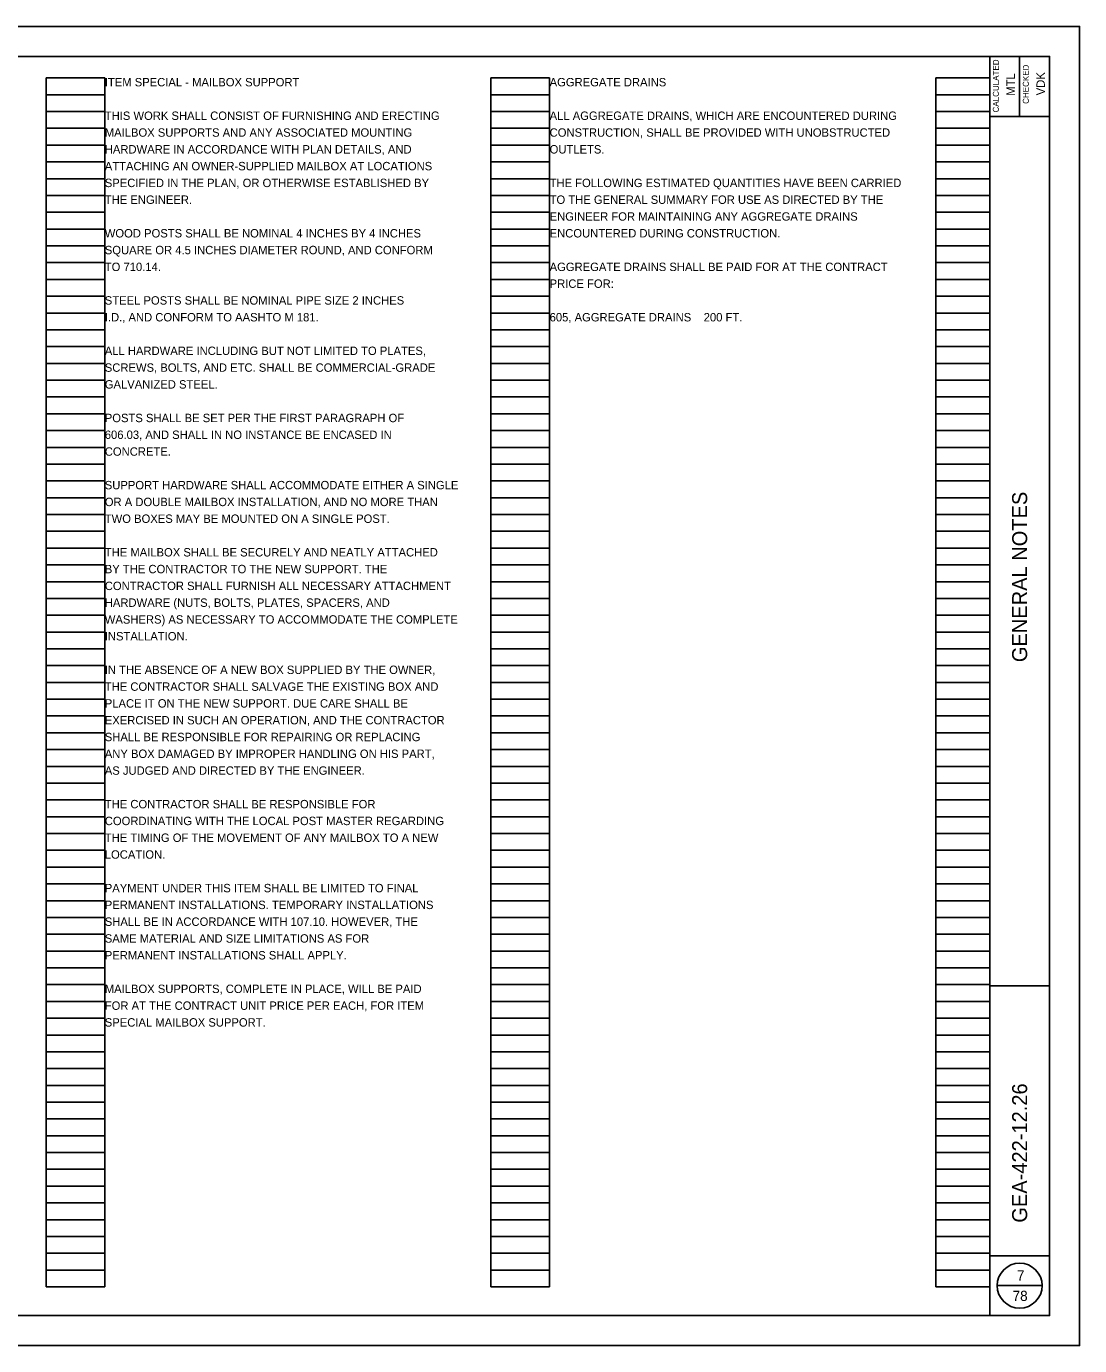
# Model space of a CAD drawing. Extents: x -13.7 to 20.3, y -10.6 to 11.4.
# Drawn here: x 2.73 to 20.3, y -10.63 to 11.37 of the extents above; entities that cross this region are included whole.
import ezdxf

# ---------------------------------------------------------------- set-up
doc = ezdxf.new("R2010")
doc.units = 0
for name, color, linetype in [('SC_Scratch1', 7, 'Continuous'), ('SH_Border', 7, 'Continuous'), ('SH_Cut_Line', 7, 'Continuous'), ('SH_Data', 7, 'Continuous'), ('SH_Text', 7, 'Continuous')]:
    doc.layers.add(name, color=color, linetype=linetype)

msp = doc.modelspace()

# ---------------------------------------------------------------- linework, layer by layer
at = {"layer": 'SC_Scratch1'}
for p, q in [((3.061, -9.649), (3.061, 10.511)), ((3.061, 10.511), (4.041, 10.511)), ((4.041, -9.649), (4.041, 10.511)), ((10.481, -9.649), (10.481, 10.511)), ((10.481, 10.511), (11.461, 10.511)), ((11.461, -9.649), (11.461, 10.511)), ((17.901, -9.649), (17.901, 10.511)), ((17.901, 10.511), (18.801, 10.511)), ((18.801, -9.649), (18.801, 10.511)), ((3.061, 10.231), (4.041, 10.231)), ((10.481, 10.231), (11.461, 10.231)), ((17.901, 10.231), (18.801, 10.231)), ((3.061, 9.951), (4.041, 9.951)), ((10.481, 9.951), (11.461, 9.951)), ((17.901, 9.951), (18.801, 9.951)), ((3.061, 9.671), (4.041, 9.671)), ((10.481, 9.671), (11.461, 9.671)), ((17.901, 9.671), (18.801, 9.671)), ((3.061, 9.391), (4.041, 9.391)), ((10.481, 9.391), (11.461, 9.391)), ((17.901, 9.391), (18.801, 9.391)), ((3.061, 9.111), (4.041, 9.111)), ((10.481, 9.111), (11.461, 9.111)), ((17.901, 9.111), (18.801, 9.111)), ((3.061, 8.831), (4.041, 8.831)), ((10.481, 8.831), (11.461, 8.831)), ((17.901, 8.831), (18.801, 8.831)), ((3.061, 8.551), (4.041, 8.551)), ((10.481, 8.551), (11.461, 8.551)), ((17.901, 8.551), (18.801, 8.551)), ((3.061, 8.271), (4.041, 8.271)), ((10.481, 8.271), (11.461, 8.271)), ((17.901, 8.271), (18.801, 8.271)), ((3.061, 7.991), (4.041, 7.991)), ((10.481, 7.991), (11.461, 7.991)), ((17.901, 7.991), (18.801, 7.991)), ((3.061, 7.711), (4.041, 7.711)), ((10.481, 7.711), (11.461, 7.711)), ((17.901, 7.711), (18.801, 7.711)), ((3.061, 7.431), (4.041, 7.431)), ((10.481, 7.431), (11.461, 7.431)), ((17.901, 7.431), (18.801, 7.431)), ((3.061, 7.151), (4.041, 7.151)), ((10.481, 7.151), (11.461, 7.151)), ((17.901, 7.151), (18.801, 7.151)), ((3.061, 6.871), (4.041, 6.871)), ((10.481, 6.871), (11.461, 6.871)), ((17.901, 6.871), (18.801, 6.871)), ((3.061, 6.591), (4.041, 6.591)), ((10.481, 6.591), (11.461, 6.591)), ((17.901, 6.591), (18.801, 6.591)), ((3.061, 6.311), (4.041, 6.311)), ((10.481, 6.311), (11.461, 6.311)), ((17.901, 6.311), (18.801, 6.311)), ((3.061, 6.031), (4.041, 6.031)), ((10.481, 6.031), (11.461, 6.031)), ((17.901, 6.031), (18.801, 6.031)), ((3.061, 5.751), (4.041, 5.751)), ((10.481, 5.751), (11.461, 5.751)), ((17.901, 5.751), (18.801, 5.751)), ((3.061, 5.471), (4.041, 5.471)), ((10.481, 5.471), (11.461, 5.471)), ((17.901, 5.471), (18.801, 5.471)), ((3.061, 5.191), (4.041, 5.191)), ((10.481, 5.191), (11.461, 5.191)), ((17.901, 5.191), (18.801, 5.191)), ((3.061, 4.911), (4.041, 4.911)), ((10.481, 4.911), (11.461, 4.911)), ((17.901, 4.911), (18.801, 4.911)), ((3.061, 4.631), (4.041, 4.631)), ((10.481, 4.631), (11.461, 4.631)), ((17.901, 4.631), (18.801, 4.631)), ((3.061, 4.351), (4.041, 4.351)), ((10.481, 4.351), (11.461, 4.351)), ((17.901, 4.351), (18.801, 4.351)), ((3.061, 4.071), (4.041, 4.071)), ((10.481, 4.071), (11.461, 4.071)), ((17.901, 4.071), (18.801, 4.071)), ((3.061, 3.791), (4.041, 3.791)), ((10.481, 3.791), (11.461, 3.791)), ((17.901, 3.791), (18.801, 3.791)), ((3.061, 3.511), (4.041, 3.511)), ((10.481, 3.511), (11.461, 3.511)), ((17.901, 3.511), (18.801, 3.511)), ((3.061, 3.231), (4.041, 3.231)), ((10.481, 3.231), (11.461, 3.231)), ((17.901, 3.231), (18.801, 3.231)), ((3.061, 2.951), (4.041, 2.951)), ((10.481, 2.951), (11.461, 2.951)), ((17.901, 2.951), (18.801, 2.951)), ((3.061, 2.671), (4.041, 2.671)), ((10.481, 2.671), (11.461, 2.671)), ((17.901, 2.671), (18.801, 2.671)), ((3.061, 2.391), (4.041, 2.391)), ((10.481, 2.391), (11.461, 2.391)), ((17.901, 2.391), (18.801, 2.391)), ((3.061, 2.111), (4.041, 2.111)), ((10.481, 2.111), (11.461, 2.111)), ((17.901, 2.111), (18.801, 2.111)), ((3.061, 1.831), (4.041, 1.831)), ((10.481, 1.831), (11.461, 1.831)), ((17.901, 1.831), (18.801, 1.831)), ((3.061, 1.551), (4.041, 1.551)), ((10.481, 1.551), (11.461, 1.551)), ((17.901, 1.551), (18.801, 1.551)), ((3.061, 1.271), (4.041, 1.271)), ((10.481, 1.271), (11.461, 1.271)), ((17.901, 1.271), (18.801, 1.271)), ((3.061, 0.991), (4.041, 0.991)), ((10.481, 0.991), (11.461, 0.991)), ((17.901, 0.991), (18.801, 0.991)), ((3.061, 0.711), (4.041, 0.711)), ((10.481, 0.711), (11.461, 0.711)), ((17.901, 0.711), (18.801, 0.711)), ((3.061, 0.431), (4.041, 0.431)), ((10.481, 0.431), (11.461, 0.431)), ((17.901, 0.431), (18.801, 0.431)), ((3.061, 0.151), (4.041, 0.151)), ((10.481, 0.151), (11.461, 0.151)), ((17.901, 0.151), (18.801, 0.151)), ((3.061, -0.129), (4.041, -0.129)), ((10.481, -0.129), (11.461, -0.129)), ((17.901, -0.129), (18.801, -0.129)), ((3.061, -0.409), (4.041, -0.409)), ((10.481, -0.409), (11.461, -0.409)), ((17.901, -0.409), (18.801, -0.409)), ((3.061, -0.689), (4.041, -0.689)), ((10.481, -0.689), (11.461, -0.689)), ((17.901, -0.689), (18.801, -0.689)), ((3.061, -0.969), (4.041, -0.969)), ((10.481, -0.969), (11.461, -0.969)), ((17.901, -0.969), (18.801, -0.969)), ((3.061, -1.249), (4.041, -1.249)), ((10.481, -1.249), (11.461, -1.249)), ((17.901, -1.249), (18.801, -1.249)), ((3.061, -1.529), (4.041, -1.529)), ((10.481, -1.529), (11.461, -1.529)), ((17.901, -1.529), (18.801, -1.529)), ((3.061, -1.809), (4.041, -1.809)), ((10.481, -1.809), (11.461, -1.809)), ((17.901, -1.809), (18.801, -1.809)), ((3.061, -2.089), (4.041, -2.089)), ((10.481, -2.089), (11.461, -2.089)), ((17.901, -2.089), (18.801, -2.089)), ((3.061, -2.369), (4.041, -2.369)), ((10.481, -2.369), (11.461, -2.369)), ((17.901, -2.369), (18.801, -2.369)), ((3.061, -2.649), (4.041, -2.649)), ((10.481, -2.649), (11.461, -2.649)), ((17.901, -2.649), (18.801, -2.649)), ((3.061, -2.929), (4.041, -2.929)), ((10.481, -2.929), (11.461, -2.929)), ((17.901, -2.929), (18.801, -2.929)), ((3.061, -3.209), (4.041, -3.209)), ((10.481, -3.209), (11.461, -3.209)), ((17.901, -3.209), (18.801, -3.209)), ((3.061, -3.489), (4.041, -3.489)), ((10.481, -3.489), (11.461, -3.489)), ((17.901, -3.489), (18.801, -3.489)), ((3.061, -3.769), (4.041, -3.769)), ((10.481, -3.769), (11.461, -3.769)), ((17.901, -3.769), (18.801, -3.769)), ((3.061, -4.049), (4.041, -4.049)), ((10.481, -4.049), (11.461, -4.049)), ((17.901, -4.049), (18.801, -4.049)), ((3.061, -4.329), (4.041, -4.329)), ((10.481, -4.329), (11.461, -4.329)), ((17.901, -4.329), (18.801, -4.329)), ((3.061, -4.609), (4.041, -4.609)), ((10.481, -4.609), (11.461, -4.609)), ((17.901, -4.609), (18.801, -4.609)), ((3.061, -4.889), (4.041, -4.889)), ((10.481, -4.889), (11.461, -4.889)), ((17.901, -4.889), (18.801, -4.889)), ((3.061, -5.169), (4.041, -5.169)), ((10.481, -5.169), (11.461, -5.169)), ((17.901, -5.169), (18.801, -5.169)), ((3.061, -5.449), (4.041, -5.449)), ((10.481, -5.449), (11.461, -5.449)), ((17.901, -5.449), (18.801, -5.449)), ((3.061, -5.729), (4.041, -5.729)), ((10.481, -5.729), (11.461, -5.729)), ((17.901, -5.729), (18.801, -5.729)), ((3.061, -6.009), (4.041, -6.009)), ((10.481, -6.009), (11.461, -6.009)), ((17.901, -6.009), (18.801, -6.009)), ((3.061, -6.289), (4.041, -6.289)), ((10.481, -6.289), (11.461, -6.289)), ((17.901, -6.289), (18.801, -6.289)), ((3.061, -6.569), (4.041, -6.569)), ((10.481, -6.569), (11.461, -6.569)), ((17.901, -6.569), (18.801, -6.569)), ((3.061, -6.849), (4.041, -6.849)), ((10.481, -6.849), (11.461, -6.849)), ((17.901, -6.849), (18.801, -6.849)), ((3.061, -7.129), (4.041, -7.129)), ((10.481, -7.129), (11.461, -7.129)), ((17.901, -7.129), (18.801, -7.129)), ((3.061, -7.409), (4.041, -7.409)), ((10.481, -7.409), (11.461, -7.409)), ((17.901, -7.409), (18.801, -7.409)), ((3.061, -7.689), (4.041, -7.689)), ((10.481, -7.689), (11.461, -7.689)), ((17.901, -7.689), (18.801, -7.689)), ((3.061, -7.969), (4.041, -7.969)), ((10.481, -7.969), (11.461, -7.969)), ((17.901, -7.969), (18.801, -7.969)), ((3.061, -8.249), (4.041, -8.249)), ((10.481, -8.249), (11.461, -8.249)), ((17.901, -8.249), (18.801, -8.249)), ((3.061, -8.529), (4.041, -8.529)), ((10.481, -8.529), (11.461, -8.529)), ((17.901, -8.529), (18.801, -8.529)), ((3.061, -8.809), (4.041, -8.809)), ((10.481, -8.809), (11.461, -8.809)), ((17.901, -8.809), (18.801, -8.809)), ((3.061, -9.089), (4.041, -9.089)), ((10.481, -9.089), (11.461, -9.089)), ((17.901, -9.089), (18.801, -9.089)), ((3.061, -9.369), (4.041, -9.369)), ((10.481, -9.369), (11.461, -9.369)), ((17.901, -9.369), (18.801, -9.369)), ((3.061, -9.649), (4.041, -9.649)), ((10.481, -9.649), (11.461, -9.649)), ((17.901, -9.649), (18.801, -9.649))]:
    msp.add_line(p, q, dxfattribs=at)
at = {"layer": 'SH_Border'}
for p, q in [((18.801, -10.129), (18.801, 10.871)), ((19.301, 10.871), (19.301, 9.871)), ((18.801, 9.871), (19.801, 9.871)), ((18.801, -4.629), (19.801, -4.629)), ((18.801, -9.129), (19.801, -9.129))]:
    msp.add_line(p, q, dxfattribs=at)
msp.add_lwpolyline([(-11.699, 10.871), (19.801, 10.871), (19.801, -10.129), (-11.699, -10.129)], close=True, dxfattribs=at)
at = {"layer": 'SH_Cut_Line'}
msp.add_lwpolyline([(-13.699, -10.629), (20.301, -10.629), (20.301, 11.371), (-13.699, 11.371)], close=True, dxfattribs=at)
at = {"layer": 'SH_Data'}
msp.add_line((18.926, -9.629), (19.676, -9.629), dxfattribs=at)
msp.add_circle((19.301, -9.629), 0.375, dxfattribs=at)

# ---------------------------------------------------------------- texts
for s, height, p in [('CALCULATED', 0.1, (18.954, 9.936)), ('MTL', 0.14, (19.221, 10.215)), ('CHECKED', 0.1, (19.454, 10.079)), ('VDK', 0.14, (19.721, 10.222)), ('GENERAL NOTES', 0.25, (19.426, 0.769)), (' GEA-422-12.26 ', 0.25, (19.426, -8.672))]:
    msp.add_text(s, height=height, rotation=90, dxfattribs=at).set_placement(p)
for s, p in [('7', (19.255, -9.544)), ('78', (19.182, -9.884))]:
    msp.add_text(s, height=0.17, dxfattribs=at).set_placement(p)
at = {"layer": 'SH_Text'}
for s, p in [('ITEM SPECIAL - MAILBOX SUPPORT', (4.041, 10.371)), ('AGGREGATE DRAINS', (11.461, 10.371)), ('THIS WORK SHALL CONSIST OF FURNISHING AND ERECTING', (4.041, 9.811)), ('ALL AGGREGATE DRAINS, WHICH ARE ENCOUNTERED DURING ', (11.461, 9.811)), ('MAILBOX SUPPORTS AND ANY ASSOCIATED MOUNTING', (4.041, 9.531)), ('CONSTRUCTION, SHALL BE PROVIDED WITH UNOBSTRUCTED ', (11.461, 9.531)), ('HARDWARE IN ACCORDANCE WITH PLAN DETAILS, AND', (4.041, 9.251)), ('OUTLETS.', (11.461, 9.251)), ('ATTACHING AN OWNER-SUPPLIED MAILBOX AT LOCATIONS', (4.041, 8.971)), ('SPECIFIED IN THE PLAN, OR OTHERWISE ESTABLISHED BY', (4.041, 8.691)), ('THE FOLLOWING ESTIMATED QUANTITIES HAVE BEEN CARRIED ', (11.461, 8.691)), ('THE ENGINEER.', (4.041, 8.411)), ('TO THE GENERAL SUMMARY FOR USE AS DIRECTED BY THE ', (11.461, 8.411)), ('ENGINEER FOR MAINTAINING ANY AGGREGATE DRAINS ', (11.461, 8.131)), ('WOOD POSTS SHALL BE NOMINAL 4 INCHES BY 4 INCHES', (4.041, 7.851)), ('ENCOUNTERED DURING CONSTRUCTION. ', (11.461, 7.851)), ('SQUARE OR 4.5 INCHES DIAMETER ROUND, AND CONFORM', (4.041, 7.571)), ('TO 710.14.', (4.041, 7.291)), ('AGGREGATE DRAINS SHALL BE PAID FOR AT THE CONTRACT ', (11.461, 7.291)), ('PRICE FOR:', (11.461, 7.011)), ('STEEL POSTS SHALL BE NOMINAL PIPE SIZE 2 INCHES', (4.041, 6.731)), ('I.D., AND CONFORM TO AASHTO M 181.', (4.041, 6.451)), ('605, AGGREGATE DRAINS    200 FT.', (11.461, 6.451)), ('ALL HARDWARE INCLUDING BUT NOT LIMITED TO PLATES,', (4.041, 5.891)), ('SCREWS, BOLTS, AND ETC. SHALL BE COMMERCIAL-GRADE', (4.041, 5.611)), ('GALVANIZED STEEL.', (4.041, 5.331)), ('POSTS SHALL BE SET PER THE FIRST PARAGRAPH OF', (4.041, 4.771)), ('606.03, AND SHALL IN NO INSTANCE BE ENCASED IN', (4.041, 4.491)), ('CONCRETE.', (4.041, 4.211)), ('SUPPORT HARDWARE SHALL ACCOMMODATE EITHER A SINGLE', (4.041, 3.651)), ('OR A DOUBLE MAILBOX INSTALLATION, AND NO MORE THAN', (4.041, 3.371)), ('TWO BOXES MAY BE MOUNTED ON A SINGLE POST.', (4.041, 3.091)), ('THE MAILBOX SHALL BE SECURELY AND NEATLY ATTACHED', (4.041, 2.531)), ('BY THE CONTRACTOR TO THE NEW SUPPORT. THE', (4.041, 2.251)), ('CONTRACTOR SHALL FURNISH ALL NECESSARY ATTACHMENT', (4.041, 1.971)), ('HARDWARE (NUTS, BOLTS, PLATES, SPACERS, AND', (4.041, 1.691)), ('WASHERS) AS NECESSARY TO ACCOMMODATE THE COMPLETE', (4.041, 1.411)), ('INSTALLATION.', (4.041, 1.131)), ('IN THE ABSENCE OF A NEW BOX SUPPLIED BY THE OWNER,', (4.041, 0.571)), ('THE CONTRACTOR SHALL SALVAGE THE EXISTING BOX AND', (4.041, 0.291)), ('PLACE IT ON THE NEW SUPPORT. DUE CARE SHALL BE', (4.041, 0.011)), ('EXERCISED IN SUCH AN OPERATION, AND THE CONTRACTOR', (4.041, -0.269)), ('SHALL BE RESPONSIBLE FOR REPAIRING OR REPLACING', (4.041, -0.549)), ('ANY BOX DAMAGED BY IMPROPER HANDLING ON HIS PART,', (4.041, -0.829)), ('AS JUDGED AND DIRECTED BY THE ENGINEER.', (4.041, -1.109)), ('THE CONTRACTOR SHALL BE RESPONSIBLE FOR', (4.041, -1.669)), ('COORDINATING WITH THE LOCAL POST MASTER REGARDING', (4.041, -1.949)), ('THE TIMING OF THE MOVEMENT OF ANY MAILBOX TO A NEW', (4.041, -2.229)), ('LOCATION.', (4.041, -2.509)), ('PAYMENT UNDER THIS ITEM SHALL BE LIMITED TO FINAL', (4.041, -3.069)), ('PERMANENT INSTALLATIONS. TEMPORARY INSTALLATIONS', (4.041, -3.349)), ('SHALL BE IN ACCORDANCE WITH 107.10. HOWEVER, THE', (4.041, -3.629)), ('SAME MATERIAL AND SIZE LIMITATIONS AS FOR', (4.041, -3.909)), ('PERMANENT INSTALLATIONS SHALL APPLY.', (4.041, -4.189)), ('MAILBOX SUPPORTS, COMPLETE IN PLACE, WILL BE PAID', (4.041, -4.749)), ('FOR AT THE CONTRACT UNIT PRICE PER EACH, FOR ITEM', (4.041, -5.029)), ('SPECIAL MAILBOX SUPPORT.', (4.041, -5.309))]:
    msp.add_text(s, height=0.14, dxfattribs=at).set_placement(p)

doc.saveas('drawing.dxf')
